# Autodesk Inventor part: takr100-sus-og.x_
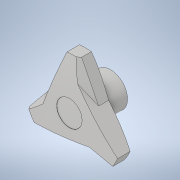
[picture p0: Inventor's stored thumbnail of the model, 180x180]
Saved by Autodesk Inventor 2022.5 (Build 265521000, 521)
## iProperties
Created: 2021-08
Part Number: takr100-sus-og.x_
Material: 一般
Document SubType Name: Modeling
Designer: ImaoCorp
Density: 1 g/cm^3
Appearance: 既定
Sending System: SOLIDWORKS 2019-2019304
MC: AMD64
MC_MODEL: Intel64 Family 6 Model 60 Stepping 3, GenuineIntel
OS: Windows_NT
FRU: Parasolid Version 31.0, build 290,  9- 1-2019
FORMAT: text
GUISE: transmit
KEY: takr100-sus-og
FILE: takr100-sus-og.x_t
DATE: Wed Aug 11 15:02:07 2021
Author: ImaoCorp
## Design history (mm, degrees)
feature "Base1"
node "ソリッド1"
